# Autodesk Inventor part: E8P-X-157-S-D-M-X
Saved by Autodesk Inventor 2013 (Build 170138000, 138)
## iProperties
Created: 2012-07
Part Number: E8P-X-157-S-D-M-X
Material: Allgemein
Document SubType Name: Modeling
Designer: rYan
Density: 1 g/cm^3
Mass: 1.6157 g
Surface Area: 16.7843 cm^2
Volume: 1.6157 cm^3
Author: rYan
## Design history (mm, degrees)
node "E8P-X-157-S-D-M-X1"
node "E8P-X-157-S-D-M-X"
node "Basis1"
